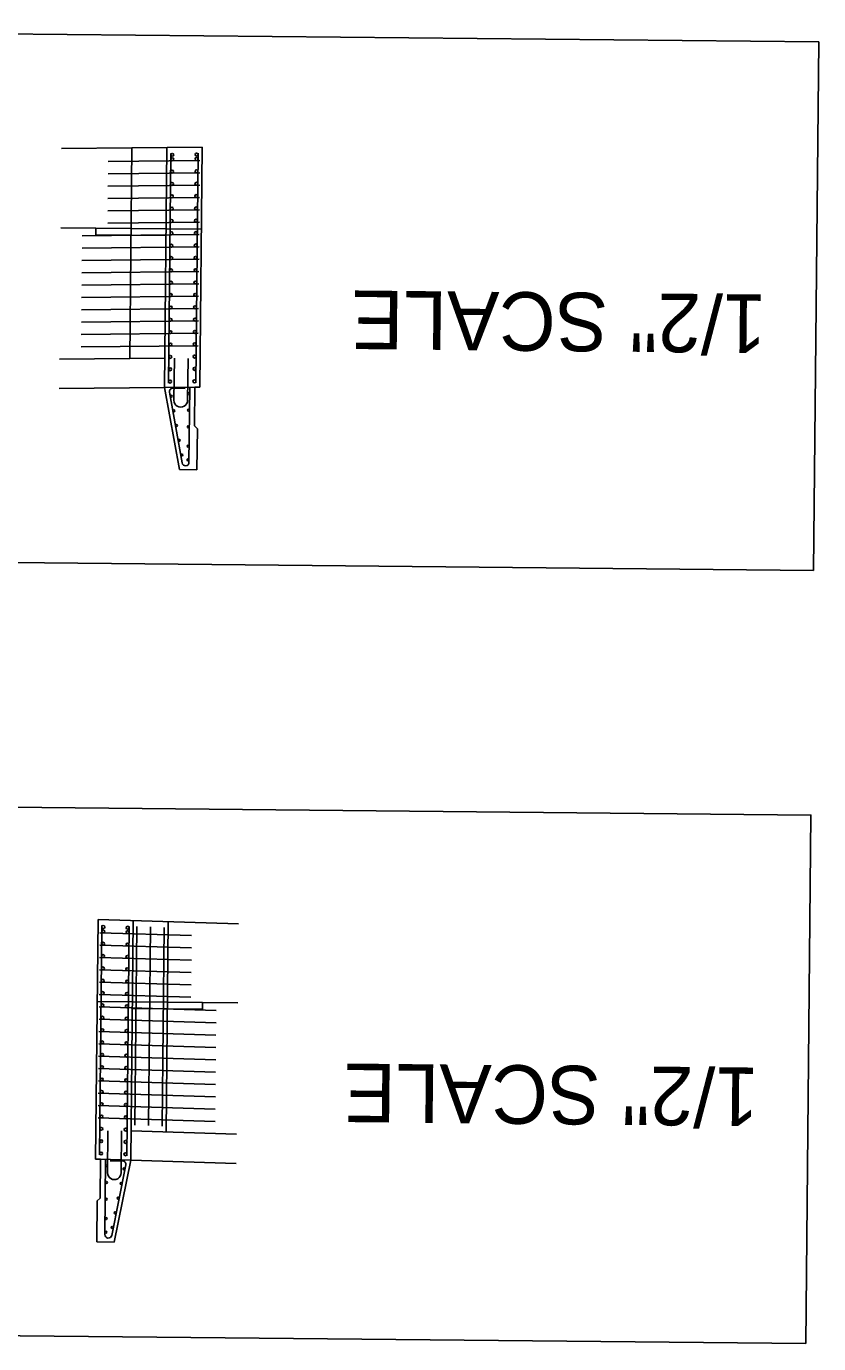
# Model space of a CAD drawing. Extents: x 631918 to 632319, y 373181 to 373282.
# Drawn here: x 631978.4 to 632012.2, y 373182.8 to 373239 of the extents above; entities that cross this region are included whole.
import ezdxf

# ---------------------------------------------------------------- set-up
doc = ezdxf.new("R2010")
doc.units = 0
for name, color, linetype in [('B_Boring', 7, 'Continuous'), ('BD-PROP-COSS', 7, 'Continuous'), ('BD-REMOVE', 7, 'Continuous'), ('R_Border_Scale', 7, 'Continuous'), ('R_Shade Removal', 7, 'Continuous')]:
    doc.layers.add(name, color=color, linetype=linetype)

msp = doc.modelspace()

# ---------------------------------------------------------------- linework, layer by layer
at = {"layer": 'B_Boring'}
for p, q in [((631984.267, 373223.578), (631984.369, 373233.817)), ((631982.822, 373190.59), (631982.924, 373200.83))]:
    msp.add_line(p, q, dxfattribs=at)
at = {"layer": 'BD-PROP-COSS'}
for p, q in [((631981.861, 373233.229), (631985.777, 373233.269)), ((631984.435, 373223.767), (631984.533, 373233.568)), ((631985.602, 373223.777), (631985.699, 373233.58)), ((631981.855, 373232.702), (631985.772, 373232.741)), ((631981.85, 373232.175), (631985.767, 373232.214)), ((631981.845, 373231.648), (631985.761, 373231.687)), ((631981.84, 373231.12), (631985.756, 373231.16)), ((631981.837, 373230.593), (631985.753, 373230.633)), ((631980.748, 373230.055), (631985.748, 373230.105)), ((631980.743, 373229.528), (631985.743, 373229.578)), ((631980.738, 373229.001), (631985.738, 373229.051)), ((631980.733, 373228.474), (631985.732, 373228.524)), ((631980.727, 373227.946), (631985.727, 373227.997)), ((631980.722, 373227.419), (631985.722, 373227.469)), ((631980.717, 373226.892), (631985.717, 373226.942)), ((631980.712, 373226.365), (631985.711, 373226.415)), ((631980.706, 373225.838), (631985.706, 373225.888)), ((631980.701, 373225.31), (631985.701, 373225.361)), ((631984.684, 373224.824), (631984.666, 373223.032)), ((631985.267, 373224.818), (631985.249, 373223.026)), ((631984.473, 373223.373), (631985.017, 373220.355)), ((631985.141, 373223.54), (631984.618, 373223.545)), ((631985.306, 373220.379), (631985.338, 373223.579)), ((631981.491, 373190.816), (631981.588, 373200.609)), ((631981.502, 373200.299), (631985.417, 373200.178)), ((631982.657, 373190.783), (631982.755, 373200.574)), ((631983.003, 373192.086), (631983.088, 373200.564)), ((631983.587, 373192.069), (631983.671, 373200.547)), ((631984.17, 373192.051), (631984.254, 373200.529)), ((631981.499, 373199.772), (631985.414, 373199.652)), ((631981.494, 373199.246), (631985.409, 373199.125)), ((631981.489, 373198.719), (631985.404, 373198.598)), ((631981.484, 373198.193), (631985.398, 373198.072)), ((631981.478, 373197.666), (631985.393, 373197.545)), ((631981.473, 373197.139), (631986.471, 373196.985)), ((631981.468, 373196.613), (631986.466, 373196.459)), ((631981.463, 373196.086), (631986.46, 373195.932)), ((631981.452, 373195.033), (631986.45, 373194.879)), ((631981.457, 373195.56), (631986.455, 373195.405)), ((631981.447, 373194.506), (631986.445, 373194.352)), ((631981.442, 373193.98), (631986.439, 373193.825)), ((631981.436, 373193.453), (631986.434, 373193.299)), ((631981.431, 373192.927), (631986.429, 373192.772)), ((631981.426, 373192.4), (631986.424, 373192.246)), ((631981.847, 373191.85), (631981.829, 373190.059)), ((631982.43, 373191.844), (631982.412, 373190.053)), ((631981.719, 373187.413), (631981.751, 373190.613)), ((631981.947, 373190.57), (631982.47, 373190.565)), ((631982.612, 373190.39), (631982.008, 373187.383))]:
    msp.add_line(p, q, dxfattribs=at)
for points in [[(632011.971, 373215.759), (631944.86, 373216.426), (631945.084, 373238.992), (632012.196, 373238.325)], [(632011.643, 373182.761), (631944.532, 373183.428), (631944.756, 373205.994), (632011.868, 373205.326)]]:
    msp.add_lwpolyline(points, close=True, dxfattribs=at)
for centre, radius in [((631984.593, 373233.318), 0.0625), ((631984.595, 373233.506), 0.0625), ((631985.634, 373233.33), 0.0625), ((631985.636, 373233.517), 0.0625), ((631984.588, 373232.791), 0.0625), ((631985.629, 373232.802), 0.0625), ((631984.582, 373232.264), 0.0625), ((631985.624, 373232.275), 0.0625), ((631984.577, 373231.737), 0.0625), ((631985.619, 373231.748), 0.0625), ((631984.572, 373231.209), 0.0625), ((631985.613, 373231.221), 0.0625), ((631984.567, 373230.682), 0.0625), ((631985.608, 373230.694), 0.0625), ((631984.561, 373230.155), 0.0625), ((631985.603, 373230.166), 0.0625), ((631984.556, 373229.628), 0.0625), ((631985.598, 373229.639), 0.0625), ((631984.551, 373229.101), 0.0625), ((631985.592, 373229.112), 0.0625), ((631984.546, 373228.573), 0.0625), ((631985.587, 373228.585), 0.0625), ((631984.54, 373228.046), 0.0625), ((631985.582, 373228.058), 0.0625), ((631984.535, 373227.519), 0.0625), ((631985.577, 373227.53), 0.0625), ((631984.525, 373226.465), 0.0625), ((631984.53, 373226.992), 0.0625), ((631985.566, 373226.476), 0.0625), ((631985.571, 373227.003), 0.0625), ((631984.519, 373225.937), 0.0625), ((631985.561, 373225.949), 0.0625), ((631984.514, 373225.41), 0.0625), ((631985.556, 373225.422), 0.0625), ((631984.509, 373224.883), 0.0625), ((631985.551, 373224.895), 0.0625), ((631984.504, 373224.356), 0.0625), ((631985.545, 373224.367), 0.0625), ((631984.499, 373223.829), 0.0625), ((631985.54, 373223.84), 0.0625), ((631984.548, 373223.2), 0.0417), ((631985.294, 373223.317), 0.0417), ((631984.661, 373222.574), 0.0417), ((631985.287, 373222.609), 0.0417), ((631984.773, 373221.948), 0.0417), ((631985.28, 373221.901), 0.0417), ((631984.886, 373221.321), 0.0417), ((631985.271, 373221.068), 0.0417), ((631984.998, 373220.695), 0.0417), ((631985.266, 373220.484), 0.0417), ((631981.648, 373200.357), 0.0625), ((631981.65, 373200.545), 0.0625), ((631982.69, 373200.325), 0.0625), ((631982.691, 373200.513), 0.0625), ((631981.643, 373199.831), 0.0625), ((631982.684, 373199.798), 0.0625), ((631981.638, 373199.304), 0.0625), ((631982.679, 373199.272), 0.0625), ((631981.633, 373198.777), 0.0625), ((631982.674, 373198.745), 0.0625), ((631981.628, 373198.251), 0.0625), ((631982.669, 373198.219), 0.0625), ((631981.622, 373197.724), 0.0625), ((631982.663, 373197.692), 0.0625), ((631981.612, 373196.671), 0.0625), ((631981.617, 373197.197), 0.0625), ((631982.658, 373197.165), 0.0625), ((631981.607, 373196.144), 0.0625), ((631982.648, 373196.112), 0.0625), ((631982.653, 373196.639), 0.0625), ((631981.601, 373195.618), 0.0625), ((631982.642, 373195.586), 0.0625), ((631981.596, 373195.091), 0.0625), ((631982.637, 373195.059), 0.0625), ((631981.591, 373194.564), 0.0625), ((631982.632, 373194.532), 0.0625), ((631981.586, 373194.038), 0.0625), ((631982.627, 373194.006), 0.0625), ((631981.58, 373193.511), 0.0625), ((631982.621, 373193.479), 0.0625), ((631981.575, 373192.985), 0.0625), ((631982.616, 373192.952), 0.0625), ((631981.57, 373192.458), 0.0625), ((631982.611, 373192.426), 0.0625), ((631981.565, 373191.931), 0.0625), ((631982.606, 373191.899), 0.0625), ((631981.559, 373191.405), 0.0625), ((631982.601, 373191.373), 0.0625), ((631981.554, 373190.878), 0.0625), ((631982.595, 373190.846), 0.0625), ((631981.79, 373190.351), 0.0417), ((631982.533, 373190.218), 0.0417), ((631981.783, 373189.642), 0.0417), ((631982.408, 373189.594), 0.0417), ((631981.776, 373188.934), 0.0417), ((631982.283, 373188.971), 0.0417), ((631982.158, 373188.347), 0.0417), ((631981.768, 373188.101), 0.0417), ((631982.034, 373187.723), 0.0417), ((631981.762, 373187.517), 0.0417)]:
    msp.add_circle(centre, radius, dxfattribs=at)
for centre, radius, start, end in [((631984.617, 373223.399), 0.146, 89.4304, 190.2146), ((631984.958, 373223.029), 0.292, 179.4304, 359.4304), ((631985.16, 373220.381), 0.146, 190.2146, 359.4304), ((631982.469, 373190.419), 0.146, 348.6461, 89.4304), ((631982.12, 373190.056), 0.292, 179.4304, 359.4304), ((631981.865, 373187.412), 0.146, 179.4304, 348.6461)]:
    msp.add_arc(centre, radius, start, end, dxfattribs=at)
at = {"layer": 'R_Border_Scale'}
for p, q in [((631982.779, 373224.813), (631982.868, 373233.802)), ((631979.778, 373224.783), (631984.279, 373224.829)), ((631984.267, 373223.578), (631985.559, 373223.591)), ((631984.334, 373191.796), (631984.423, 373200.785)), ((631987.334, 373191.706), (631982.834, 373191.841)), ((631982.822, 373190.59), (631981.531, 373190.629))]:
    msp.add_line(p, q, dxfattribs=at)
at = {"layer": 'R_Shade Removal'}
for p, q in [((631979.868, 373233.772), (631985.869, 373233.832)), ((631985.767, 373223.593), (631985.869, 373233.832)), ((631985.834, 373230.332), (631979.834, 373230.392)), ((631981.332, 373230.099), (631981.334, 373230.377)), ((631984.331, 373230.069), (631981.332, 373230.099)), ((631979.766, 373223.532), (631984.267, 373223.578)), ((631984.267, 373223.578), (631984.899, 373220.071)), ((631985.542, 373221.94), (631985.559, 373223.591)), ((631985.559, 373223.591), (631985.767, 373223.593)), ((631985.666, 373221.814), (631985.542, 373221.94)), ((631985.649, 373220.064), (631985.666, 373221.814)), ((631984.899, 373220.071), (631985.649, 373220.064)), ((631981.323, 373190.635), (631981.424, 373200.864)), ((631987.423, 373200.684), (631981.424, 373200.864)), ((631981.39, 373197.364), (631987.389, 373197.305)), ((631985.886, 373197.041), (631985.889, 373197.319)), ((631982.886, 373197.071), (631985.886, 373197.041)), ((631981.531, 373190.629), (631981.323, 373190.635)), ((631981.514, 373188.978), (631981.531, 373190.629)), ((631982.822, 373190.59), (631982.12, 373187.097)), ((631987.321, 373190.456), (631982.822, 373190.59)), ((631981.371, 373187.105), (631981.388, 373188.855)), ((631981.388, 373188.855), (631981.514, 373188.978)), ((631982.12, 373187.097), (631981.371, 373187.105))]:
    msp.add_line(p, q, dxfattribs=at)

# ---------------------------------------------------------------- texts
at = {"layer": 'BD-REMOVE'}
for p in [(632009.975, 373227.543), (632009.647, 373194.544)]:
    msp.add_text('1/2" SCALE', height=2.5, rotation=179.4304, dxfattribs=at).set_placement(p)

doc.saveas('drawing.dxf')
